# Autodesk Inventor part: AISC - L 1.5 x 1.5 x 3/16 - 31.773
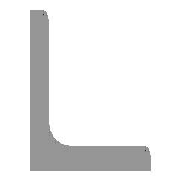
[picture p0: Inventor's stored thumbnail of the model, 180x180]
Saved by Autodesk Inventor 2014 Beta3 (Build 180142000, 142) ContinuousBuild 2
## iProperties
IsCustomPart: 1
Created: 2010-11
Part Number: AISC - L 1.5 x 1.5 x 3/16 - 31.773
Material: Steel, Mild
Description: Angle Steel
Document SubType Name: Modeling
Standard: ANSI
Designer: Beta-8540w
Standards Organization: ANSI
Language: en-US
Size Designation: L 1.5 x 1.5 x 3/16
Categories: <MemberInstance><Categories><Category DisplayName="Structural Shapes" InternalName="089c4875-fa83-4c05-b084-43b9cc11f5ed" Mnemonic="GRDR"><CategoryParameter Dis
Stock Number: L 1.5 x 1.5 x 3/16
Density: 7.86 g/cm^3
Appearance: Steel
_CCFamilyMember: 5
_CCFamilyDisplayName: ANSI L (Equal angles) - Angle Steel
_FrameMemberDoc: Frame Member File
_Version: 15.0.0
_GetPNFromCC: 1
G_L: 31.773 in
G_W: 1.500 in
G_H: 1.500 in
+5968F0EF-F5AD-46F6-A5DD-B649BA20EEC9+CUTDETAIL1: Cut
Author: Beta-8540w
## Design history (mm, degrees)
node "Start plane"
node "End plane"
sketch "Sketch"
  geometry: L1 (38.1, 0)-(0, 0); L2 (0, 0)-(0, 38.1); L3 (0, 38.1)-(2.476, 38.1); L4 (4.762, 35.814)-(4.762, 9.589); L5 (9.588, 4.763)-(35.814, 4.763); L6 (38.1, 2.477)-(38.1, 0); L7 (0, -11.041)-(0, 31.538); L8 (-11.041, 0)-(31.538, 0); L9 (0, 48.496)-(0, -20.964) reference; L10 (-20.964, 0)-(48.496, 0) reference; A1 r 4.826 centre (9.588, 9.589) between (4.762, 9.589) and (9.588, 4.763); A2 r 2.286 centre (2.476, 35.814) between (4.762, 35.814) and (2.476, 38.1); A3 r 2.286 centre (35.814, 2.477) between (38.1, 2.477) and (35.814, 4.763); 3 further points
  constraints: 16 end point, 6 point on circle, 6 point on line, 6 tangent, 4 parallel, 3 centre point, 2 collinear, 1 equal radius, 1 horizontal, 1 perpendicular
  dimensions: "d0" = 38.1 distance between parallel lines of L6 L2 (= G_H); "d1" = 38.1 distance between parallel lines of L3 L1 (= G_H); "d2" = 4.7625 distance between parallel lines of L2 L4 (= G_T); "d3" = 4.7625 distance between parallel lines of L1 L5 (= G_T); "d10" = 0 distance between parallel lines of L7 L2 (computed from ex); "d11" = 0 distance between parallel lines of L8 L1 (computed from d10); "d14" = 4.826 radius of A1 (= G_IR); "d15" = 2.286 radius of A2 (= G_ER)
extrude "Body" new body sketch "Sketch" stored distance "d4" = 807.0404 (= G_L); taper "d5" = 0 deg
node "Driven Length"
  sketch "Sketch3"
    geometry: L1 (0, 0)-(10, 0) reference
    constraints: 2 end point, 1 horizontal
  workplane "Work Plane3"
  sketch "Sketch4"
    geometry: L1 (-2, 0)-(12, 0) reference; L2 (-2, 807.04)-(12, 807.04) reference
    dimensions: "d17" = 807.0404 distance between parallel lines of L1 L2 (derived)
workplane "Work Plane4"
split "Split1"
body "Solid1"
other parameters: "G_H" = 38.1 [user parameter; used in 2 equation terms], "G_T" = 4.7625 [user parameter; used in 2 equation terms], "G_ER" = 2.286 [user parameter; used in 1 equation term], "G_IR" = 4.826 [user parameter; used in 1 equation term], "G_L" = 807.0404 (= d17) [user parameter; used in 1 equation term], "ex" = 0 [user parameter; used in 1 equation term], "G_OFFSET_START" = 0 [user parameter; used in 1 equation term], "G_OFFSET_END" = -29.72503 [user parameter; used in 1 equation term], "d12" = 0 (computed from G_OFFSET_START), "d13" = 807.0404 (= G_OFFSET_END + B_L), "B_L" = 836.76542 [user parameter; used in 1 equation term], "d16" = 90 deg, "MAS" = 0.26787 [user parameter]
